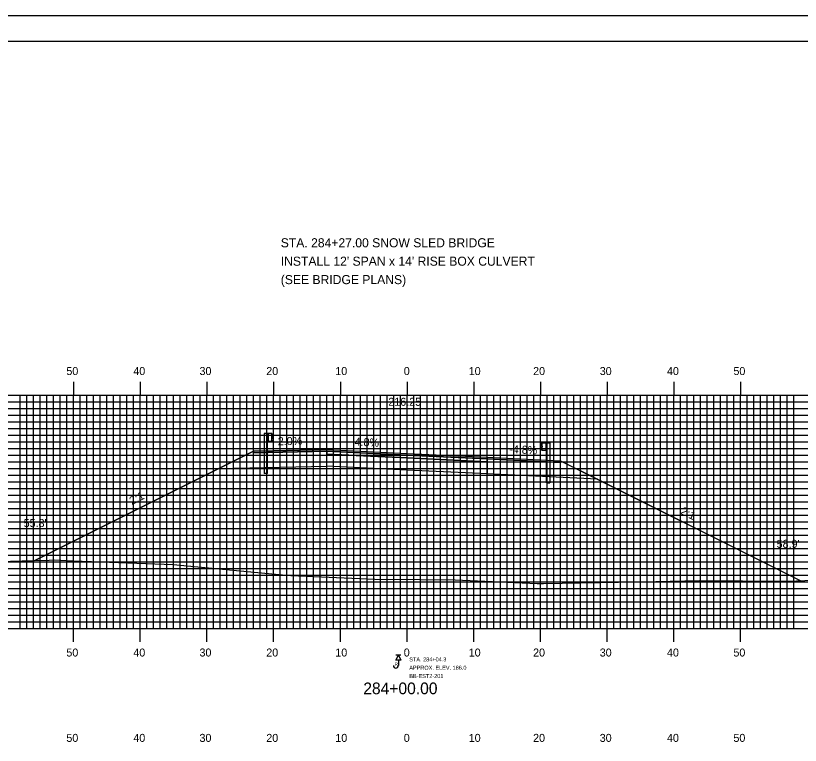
# Model space of a CAD drawing. Extents: x 1811767 to 1812110, y 442591 to 442811.
# Drawn here: x 1811874.3 to 1811991.9, y 442701.2 to 442810.5 of the extents above; entities that cross this region are included whole.
import ezdxf

# ---------------------------------------------------------------- set-up
doc = ezdxf.new("R2010")
doc.units = 0
for name, color, linetype in [('ANNOTATION', 7, 'Continuous'), ('BORDER', 7, 'Continuous'), ('D_Guardrail_Beam_Lt', 7, 'Continuous'), ('D_Guardrail_Beam_Rt', 7, 'Continuous'), ('D_Roadway_Centerline', 7, 'Continuous'), ('D_Roadway_Centerline_Text', 7, 'Continuous'), ('D_Roadway_Edge_Shoulder', 7, 'Continuous'), ('D_Roadway_Edge_TW', 7, 'Continuous'), ('D_Roadway_Pavement', 7, 'Continuous'), ('D_Roadway_SlopeLines', 7, 'Continuous'), ('D_Roadway_SubGrade', 7, 'Continuous'), ('D_Text_Standard', 7, 'Continuous'), ('H_V ANNOTATION', 7, 'Continuous'), ('MAJOR', 7, 'Continuous'), ('MINOR', 7, 'Continuous'), ('PLOT BOUNDARY', 7, 'Continuous'), ('ROCKS', 7, 'Continuous'), ('S_Roadway_Centerline', 7, 'Continuous')]:
    doc.layers.add(name, color=color, linetype=linetype)

msp = doc.modelspace()

# ---------------------------------------------------------------- linework, layer by layer
at = {"layer": 'BORDER'}
msp.add_lwpolyline([(1811783.32, 442596.67), (1812103.32, 442596.67), (1812103.32, 442806.67), (1811783.32, 442806.67)], close=True, dxfattribs=at)
at = {"layer": 'D_Guardrail_Beam_Lt'}
for p, q in [((1811911.49, 442747.91), (1811911.49, 442741.91)), ((1811911.96, 442747.91), (1811911.49, 442747.91)), ((1811912.65, 442747.91), (1811911.96, 442747.91)), ((1811911.96, 442747.91), (1811911.96, 442746.74)), ((1811912.02, 442747.91), (1811912.02, 442746.74)), ((1811912.12, 442747.91), (1811912.12, 442746.74)), ((1811912.65, 442746.74), (1811912.65, 442747.91)), ((1811912.65, 442747.83), (1811912.72, 442747.81)), ((1811912.65, 442747.36), (1811912.65, 442747.29)), ((1811912.88, 442747.56), (1811912.68, 442747.43)), ((1811912.68, 442747.23), (1811912.88, 442747.09)), ((1811912.74, 442747.81), (1811912.88, 442747.71)), ((1811912.88, 442746.95), (1811912.74, 442746.85)), ((1811911.96, 442746.74), (1811912.65, 442746.74)), ((1811911.98, 442741.91), (1811911.98, 442746.74)), ((1811912.72, 442746.84), (1811912.65, 442746.83)), ((1811911.98, 442741.91), (1811911.49, 442741.91))]:
    msp.add_line(p, q, dxfattribs=at)
for centre, major_axis, start_param, end_param in [((1811912.73, 442747.36), (-0.0789, 0), 5.323254, 6.283185), ((1811912.73, 442747.29), (-0.0789, 0), 6.283185, 7.243116), ((1811912.71, 442747.77), (0.0417, 0), 0.959931, 1.376053), ((1811912.83, 442747.63), (0.0877, 0), 5.323254, 7.243116), ((1811912.83, 442747.02), (0.0877, 0), 5.323254, 7.243116), ((1811912.71, 442746.88), (0.0417, 0), 4.907132, 5.323254)]:
    msp.add_ellipse(centre, major_axis=major_axis, ratio=0.995501, start_param=start_param, end_param=end_param, dxfattribs=at)
at = {"layer": 'D_Guardrail_Beam_Rt'}
for p, q in [((1811953.1, 442746.43), (1811952.95, 442746.33)), ((1811952.95, 442746.19), (1811953.15, 442746.05)), ((1811953.15, 442745.85), (1811952.95, 442745.72)), ((1811953.19, 442746.45), (1811953.11, 442746.44)), ((1811953.18, 442745.99), (1811953.18, 442745.92)), ((1811953.19, 442746.53), (1811953.87, 442746.53)), ((1811953.19, 442745.37), (1811953.19, 442746.53)), ((1811953.71, 442746.53), (1811953.71, 442745.37)), ((1811953.81, 442746.53), (1811953.81, 442745.37)), ((1811953.87, 442746.53), (1811954.35, 442746.53)), ((1811953.87, 442746.53), (1811953.87, 442745.37)), ((1811954.35, 442746.53), (1811954.35, 442740.53)), ((1811952.95, 442745.57), (1811953.1, 442745.47)), ((1811953.11, 442745.47), (1811953.19, 442745.45)), ((1811953.87, 442745.37), (1811953.19, 442745.37)), ((1811953.85, 442740.53), (1811953.85, 442745.37)), ((1811953.85, 442740.53), (1811954.35, 442740.53))]:
    msp.add_line(p, q, dxfattribs=at)
for centre, major_axis, start_param, end_param in [((1811953, 442746.26), (-0.0877, 0), 5.323254, 7.243116), ((1811953, 442745.64), (-0.0877, 0), 5.323254, 7.243116), ((1811953.12, 442746.4), (-0.0417, 0), 4.907132, 5.323254), ((1811953.1, 442745.99), (0.0789, 0), 0, 0.959931), ((1811953.1, 442745.92), (0.0789, 0), 5.323254, 6.283185), ((1811953.12, 442745.51), (-0.0417, 0), 0.959931, 1.376053)]:
    msp.add_ellipse(centre, major_axis=major_axis, ratio=0.995501, start_param=start_param, end_param=end_param, dxfattribs=at)
at = {"layer": 'D_Roadway_Centerline'}
msp.add_lwpolyline([(1811877.12, 442728.87), (1811904.71, 442742.66), (1811909.92, 442745.27), (1811912.92, 442745.33), (1811920.92, 442745.49), (1811932.92, 442744.91), (1811944.92, 442744.34), (1811952.92, 442743.95), (1811955.92, 442743.81), (1811961.45, 442741.04), (1811991.84, 442725.85)], dxfattribs=at)
at = {"layer": 'D_Roadway_Edge_Shoulder'}
for points in [[(1811920.92, 442745.49), (1811912.92, 442745.33), (1811912.92, 442745.33), (1811909.92, 442745.27), (1811909.92, 442745.02), (1811920.92, 442745.24)], [(1811944.92, 442744.34), (1811952.92, 442743.95), (1811952.92, 442743.95), (1811955.92, 442743.81), (1811955.92, 442743.56), (1811944.92, 442744.09)]]:
    msp.add_lwpolyline(points, close=True, dxfattribs=at)
at = {"layer": 'D_Roadway_Edge_TW'}
msp.add_lwpolyline([(1811920.92, 442745.24), (1811920.92, 442745.49), (1811932.92, 442744.91), (1811944.92, 442744.34), (1811944.92, 442744.09), (1811932.92, 442744.66)], close=True, dxfattribs=at)
at = {"layer": 'D_Roadway_Pavement'}
msp.add_lwpolyline([(1811920.92, 442744.82), (1811920.92, 442745.24), (1811932.92, 442744.66), (1811944.92, 442744.09), (1811944.92, 442743.67), (1811932.92, 442744.24)], close=True, dxfattribs=at)
for points in [[(1811920.92, 442745.24), (1811920.92, 442744.82)], [(1811944.92, 442744.09), (1811944.92, 442743.67)]]:
    msp.add_lwpolyline(points, dxfattribs=at)
at = {"layer": 'D_Roadway_SlopeLines'}
for points in [[(1811909.92, 442745.27), (1811877.12, 442728.87)], [(1811955.92, 442743.81), (1811991.84, 442725.85)]]:
    msp.add_lwpolyline(points, dxfattribs=at)
at = {"layer": 'D_Roadway_SubGrade'}
for points in [[(1811920.92, 442744.82), (1811920.92, 442745.24), (1811909.92, 442745.02), (1811909.92, 442745.27), (1811904.71, 442742.66), (1811920.92, 442742.99)], [(1811920.92, 442742.99), (1811920.92, 442745.24), (1811920.92, 442744.82), (1811932.92, 442744.24), (1811944.92, 442743.67), (1811944.92, 442744.09), (1811944.92, 442741.84), (1811932.92, 442742.41)], [(1811944.92, 442743.67), (1811944.92, 442744.09), (1811955.92, 442743.56), (1811955.92, 442743.81), (1811961.45, 442741.04), (1811944.92, 442741.84)]]:
    msp.add_lwpolyline(points, close=True, dxfattribs=at)
at = {"layer": 'MAJOR'}
for p, q in [((1811882.92, 442755.67), (1811882.92, 442753.67)), ((1811892.92, 442755.67), (1811892.92, 442753.67)), ((1811902.92, 442755.67), (1811902.92, 442753.67)), ((1811912.92, 442755.67), (1811912.92, 442753.67)), ((1811922.92, 442755.67), (1811922.92, 442753.67)), ((1811932.92, 442755.67), (1811932.92, 442753.67)), ((1811942.92, 442755.67), (1811942.92, 442753.67)), ((1811952.92, 442755.67), (1811952.92, 442753.67)), ((1811962.92, 442755.67), (1811962.92, 442753.67)), ((1811972.92, 442755.67), (1811972.92, 442753.67)), ((1811982.92, 442755.67), (1811982.92, 442753.67)), ((1811792.92, 442753.67), (1812072.92, 442753.67)), ((1811792.92, 442753.67), (1812072.92, 442753.67)), ((1811882.92, 442718.67), (1811882.92, 442753.67)), ((1811892.92, 442718.67), (1811892.92, 442753.67)), ((1811902.92, 442718.67), (1811902.92, 442753.67)), ((1811912.92, 442718.67), (1811912.92, 442753.67)), ((1811922.92, 442718.67), (1811922.92, 442753.67)), ((1811932.92, 442718.67), (1811932.92, 442753.67)), ((1811942.92, 442718.67), (1811942.92, 442753.67)), ((1811952.92, 442718.67), (1811952.92, 442753.67)), ((1811962.92, 442718.67), (1811962.92, 442753.67)), ((1811972.92, 442718.67), (1811972.92, 442753.67)), ((1811982.92, 442718.67), (1811982.92, 442753.67)), ((1811792.92, 442748.67), (1812072.92, 442748.67)), ((1811792.92, 442743.67), (1812072.92, 442743.67)), ((1811792.92, 442738.67), (1812072.92, 442738.67)), ((1811792.92, 442733.67), (1812072.92, 442733.67)), ((1811792.92, 442728.67), (1812072.92, 442728.67)), ((1811792.92, 442723.67), (1812072.92, 442723.67)), ((1811792.92, 442718.67), (1812072.92, 442718.67)), ((1811792.92, 442718.67), (1812072.92, 442718.67)), ((1811882.92, 442716.66), (1811882.92, 442718.67)), ((1811892.92, 442716.66), (1811892.92, 442718.67)), ((1811902.92, 442716.66), (1811902.92, 442718.67)), ((1811912.92, 442716.66), (1811912.92, 442718.67)), ((1811922.92, 442716.66), (1811922.92, 442718.67)), ((1811932.92, 442716.66), (1811932.92, 442718.67)), ((1811942.92, 442716.66), (1811942.92, 442718.67)), ((1811952.92, 442716.66), (1811952.92, 442718.67)), ((1811962.92, 442716.66), (1811962.92, 442718.67)), ((1811972.92, 442716.66), (1811972.92, 442718.67)), ((1811982.92, 442716.66), (1811982.92, 442718.67))]:
    msp.add_line(p, q, dxfattribs=at)
at = {"layer": 'MINOR'}
for p, q in [((1811874.92, 442718.67), (1811874.92, 442753.67)), ((1811875.92, 442718.67), (1811875.92, 442753.67)), ((1811876.92, 442718.67), (1811876.92, 442753.67)), ((1811877.92, 442718.67), (1811877.92, 442753.67)), ((1811878.92, 442718.67), (1811878.92, 442753.67)), ((1811879.92, 442718.67), (1811879.92, 442753.67)), ((1811880.92, 442718.67), (1811880.92, 442753.67)), ((1811881.92, 442718.67), (1811881.92, 442753.67)), ((1811883.92, 442718.67), (1811883.92, 442753.67)), ((1811884.92, 442718.67), (1811884.92, 442753.67)), ((1811885.92, 442718.67), (1811885.92, 442753.67)), ((1811886.92, 442718.67), (1811886.92, 442753.67)), ((1811887.92, 442718.67), (1811887.92, 442753.67)), ((1811888.92, 442718.67), (1811888.92, 442753.67)), ((1811889.92, 442718.67), (1811889.92, 442753.67)), ((1811890.92, 442718.67), (1811890.92, 442753.67)), ((1811891.92, 442718.67), (1811891.92, 442753.67)), ((1811893.92, 442718.67), (1811893.92, 442753.67)), ((1811894.92, 442718.67), (1811894.92, 442753.67)), ((1811895.92, 442718.67), (1811895.92, 442753.67)), ((1811896.92, 442718.67), (1811896.92, 442753.67)), ((1811897.92, 442718.67), (1811897.92, 442753.67)), ((1811898.92, 442718.67), (1811898.92, 442753.67)), ((1811899.92, 442718.67), (1811899.92, 442753.67)), ((1811900.92, 442718.67), (1811900.92, 442753.67)), ((1811901.92, 442718.67), (1811901.92, 442753.67)), ((1811903.92, 442718.67), (1811903.92, 442753.67)), ((1811904.92, 442718.67), (1811904.92, 442753.67)), ((1811905.92, 442718.67), (1811905.92, 442753.67)), ((1811906.92, 442718.67), (1811906.92, 442753.67)), ((1811907.92, 442718.67), (1811907.92, 442753.67)), ((1811908.92, 442718.67), (1811908.92, 442753.67)), ((1811909.92, 442718.67), (1811909.92, 442753.67)), ((1811910.92, 442718.67), (1811910.92, 442753.67)), ((1811911.92, 442718.67), (1811911.92, 442753.67)), ((1811913.92, 442718.67), (1811913.92, 442753.67)), ((1811914.92, 442718.67), (1811914.92, 442753.67)), ((1811915.92, 442718.67), (1811915.92, 442753.67)), ((1811916.92, 442718.67), (1811916.92, 442753.67)), ((1811917.92, 442718.67), (1811917.92, 442753.67)), ((1811918.92, 442718.67), (1811918.92, 442753.67)), ((1811919.92, 442718.67), (1811919.92, 442753.67)), ((1811920.92, 442718.67), (1811920.92, 442753.67)), ((1811921.92, 442718.67), (1811921.92, 442753.67)), ((1811923.92, 442718.67), (1811923.92, 442753.67)), ((1811924.92, 442718.67), (1811924.92, 442753.67)), ((1811925.92, 442718.67), (1811925.92, 442753.67)), ((1811926.92, 442718.67), (1811926.92, 442753.67)), ((1811927.92, 442718.67), (1811927.92, 442753.67)), ((1811928.92, 442718.67), (1811928.92, 442753.67)), ((1811929.92, 442718.67), (1811929.92, 442753.67)), ((1811930.92, 442718.67), (1811930.92, 442753.67)), ((1811931.92, 442718.67), (1811931.92, 442753.67)), ((1811933.92, 442718.67), (1811933.92, 442753.67)), ((1811934.92, 442718.67), (1811934.92, 442753.67)), ((1811935.92, 442718.67), (1811935.92, 442753.67)), ((1811936.92, 442718.67), (1811936.92, 442753.67)), ((1811937.92, 442718.67), (1811937.92, 442753.67)), ((1811938.92, 442718.67), (1811938.92, 442753.67)), ((1811939.92, 442718.67), (1811939.92, 442753.67)), ((1811940.92, 442718.67), (1811940.92, 442753.67)), ((1811941.92, 442718.67), (1811941.92, 442753.67)), ((1811943.92, 442718.67), (1811943.92, 442753.67)), ((1811944.92, 442718.67), (1811944.92, 442753.67)), ((1811945.92, 442718.67), (1811945.92, 442753.67)), ((1811946.92, 442718.67), (1811946.92, 442753.67)), ((1811947.92, 442718.67), (1811947.92, 442753.67)), ((1811948.92, 442718.67), (1811948.92, 442753.67)), ((1811949.92, 442718.67), (1811949.92, 442753.67)), ((1811950.92, 442718.67), (1811950.92, 442753.67)), ((1811951.92, 442718.67), (1811951.92, 442753.67)), ((1811953.92, 442718.67), (1811953.92, 442753.67)), ((1811954.92, 442718.67), (1811954.92, 442753.67)), ((1811955.92, 442718.67), (1811955.92, 442753.67)), ((1811956.92, 442718.67), (1811956.92, 442753.67)), ((1811957.92, 442718.67), (1811957.92, 442753.67)), ((1811958.92, 442718.67), (1811958.92, 442753.67)), ((1811959.92, 442718.67), (1811959.92, 442753.67)), ((1811960.92, 442718.67), (1811960.92, 442753.67)), ((1811961.92, 442718.67), (1811961.92, 442753.67)), ((1811963.92, 442718.67), (1811963.92, 442753.67)), ((1811964.92, 442718.67), (1811964.92, 442753.67)), ((1811965.92, 442718.67), (1811965.92, 442753.67)), ((1811966.92, 442718.67), (1811966.92, 442753.67)), ((1811967.92, 442718.67), (1811967.92, 442753.67)), ((1811968.92, 442718.67), (1811968.92, 442753.67)), ((1811969.92, 442718.67), (1811969.92, 442753.67)), ((1811970.92, 442718.67), (1811970.92, 442753.67)), ((1811971.92, 442718.67), (1811971.92, 442753.67)), ((1811973.92, 442718.67), (1811973.92, 442753.67)), ((1811974.92, 442718.67), (1811974.92, 442753.67)), ((1811975.92, 442718.67), (1811975.92, 442753.67)), ((1811976.92, 442718.67), (1811976.92, 442753.67)), ((1811977.92, 442718.67), (1811977.92, 442753.67)), ((1811978.92, 442718.67), (1811978.92, 442753.67)), ((1811979.92, 442718.67), (1811979.92, 442753.67)), ((1811980.92, 442718.67), (1811980.92, 442753.67)), ((1811981.92, 442718.67), (1811981.92, 442753.67)), ((1811983.92, 442718.67), (1811983.92, 442753.67)), ((1811984.92, 442718.67), (1811984.92, 442753.67)), ((1811985.92, 442718.67), (1811985.92, 442753.67)), ((1811986.92, 442718.67), (1811986.92, 442753.67)), ((1811987.92, 442718.67), (1811987.92, 442753.67)), ((1811988.92, 442718.67), (1811988.92, 442753.67)), ((1811989.92, 442718.67), (1811989.92, 442753.67)), ((1811990.92, 442718.67), (1811990.92, 442753.67)), ((1811792.92, 442752.67), (1812072.92, 442752.67)), ((1811792.92, 442751.67), (1812072.92, 442751.67)), ((1811792.92, 442750.67), (1812072.92, 442750.67)), ((1811792.92, 442749.67), (1812072.92, 442749.67)), ((1811792.92, 442747.67), (1812072.92, 442747.67)), ((1811792.92, 442746.67), (1812072.92, 442746.67)), ((1811792.92, 442745.67), (1812072.92, 442745.67)), ((1811792.92, 442744.67), (1812072.92, 442744.67)), ((1811792.92, 442742.67), (1812072.92, 442742.67)), ((1811792.92, 442741.67), (1812072.92, 442741.67)), ((1811792.92, 442740.67), (1812072.92, 442740.67)), ((1811792.92, 442739.67), (1812072.92, 442739.67)), ((1811792.92, 442737.67), (1812072.92, 442737.67)), ((1811792.92, 442736.67), (1812072.92, 442736.67)), ((1811792.92, 442735.67), (1812072.92, 442735.67)), ((1811792.92, 442734.67), (1812072.92, 442734.67)), ((1811792.92, 442732.67), (1812072.92, 442732.67)), ((1811792.92, 442731.67), (1812072.92, 442731.67)), ((1811792.92, 442730.67), (1812072.92, 442730.67)), ((1811792.92, 442729.67), (1812072.92, 442729.67)), ((1811792.92, 442727.67), (1812072.92, 442727.67)), ((1811792.92, 442726.67), (1812072.92, 442726.67)), ((1811792.92, 442725.67), (1812072.92, 442725.67)), ((1811792.92, 442724.67), (1812072.92, 442724.67)), ((1811792.92, 442722.67), (1812072.92, 442722.67)), ((1811792.92, 442721.67), (1812072.92, 442721.67)), ((1811792.92, 442720.67), (1812072.92, 442720.67)), ((1811792.92, 442719.67), (1812072.92, 442719.67))]:
    msp.add_line(p, q, dxfattribs=at)
at = {"layer": 'PLOT BOUNDARY'}
msp.add_lwpolyline([(1811767.13, 442590.55), (1812107.13, 442590.55), (1812107.13, 442810.55), (1811767.13, 442810.55)], close=True, dxfattribs=at)
at = {"layer": 'ROCKS'}
for p, q in [((1811931.98, 442714.67), (1811931.25, 442714.67)), ((1811931.62, 442713.93), (1811931.62, 442713.11))]:
    msp.add_line(p, q, dxfattribs=at)
msp.add_lwpolyline([(1811931.62, 442714.67), (1811931.98, 442713.93), (1811931.25, 442713.93)], close=True, dxfattribs=at)
msp.add_arc((1811931.24, 442713.11), 0.373, 180, 0, dxfattribs=at)
at = {"layer": 'S_Roadway_Centerline'}
msp.add_lwpolyline([(1811861.44, 442728.43), (1811876.92, 442728.86), (1811879.28, 442728.94), (1811880.11, 442728.97), (1811882.85, 442728.82), (1811897.88, 442728.29), (1811914.26, 442726.71), (1811915.52, 442726.63), (1811928.09, 442726.07), (1811934.83, 442726), (1811940.13, 442725.97), (1811952.44, 442725.4), (1811953.36, 442725.42), (1811970.2, 442725.74), (1811976.7, 442725.87), (1811989.7, 442725.78), (1811990.06, 442725.78), (1812001.38, 442726.22)], dxfattribs=at)

# ---------------------------------------------------------------- texts
at = {"layer": 'ANNOTATION'}
for s, p in [('STA. 284+27.00 SNOW SLED BRIDGE', (1811913.99, 442775.82)), ("INSTALL 12' SPAN x 14' RISE BOX CULVERT", (1811913.99, 442773.06)), ('(SEE BRIDGE PLANS)', (1811913.99, 442770.3))]:
    msp.add_text(s, height=1.36, dxfattribs=at).set_placement(p)
for s, rotation, p in [('-2.0%', 1.1458, (1811913.02, 442746.13)), ('4.8%', 357.2519, (1811925.04, 442746.09)), ('-4.8%', 357.2519, (1811948.22, 442744.98)), ('2:1', 26.5651, (1811891.66, 442737.18)), ('2:1', 333.4349, (1811973.81, 442735.9))]:
    msp.add_text(s, height=1.2, rotation=rotation, dxfattribs=at).set_placement(p)
at = {"layer": 'D_Roadway_Centerline'}
for s, p in [('C', (1811932.91, 442744.91)), ('L', (1811932.92, 442744.9))]:
    msp.add_text(s, height=0.0146, dxfattribs=at).set_placement(p)
at = {"layer": 'D_Roadway_Centerline_Text'}
msp.add_text('216.25', height=1.2, dxfattribs=at).set_placement((1811930.12, 442752.06))
at = {"layer": 'D_Text_Standard'}
for s, p in [("55.8'", (1811875.45, 442733.88)), ("58.9'", (1811988.33, 442730.76))]:
    msp.add_text(s, height=1.2, dxfattribs=at).set_placement(p)
at = {"layer": 'H_V ANNOTATION'}
for s, height, p in [('50', 1.2, (1811881.85, 442756.67)), ('40', 1.2, (1811891.89, 442756.67)), ('30', 1.2, (1811901.81, 442756.67)), ('20', 1.2, (1811911.82, 442756.67)), ('10', 1.2, (1811922.17, 442756.67)), ('0', 1.2, (1811932.43, 442756.67)), ('10', 1.2, (1811942.17, 442756.67)), ('20', 1.2, (1811951.82, 442756.67)), ('30', 1.2, (1811961.81, 442756.67)), ('40', 1.2, (1811971.89, 442756.67)), ('50', 1.2, (1811981.85, 442756.67)), ('50', 1.2, (1811881.85, 442714.47)), ('40', 1.2, (1811891.89, 442714.47)), ('30', 1.2, (1811901.81, 442714.47)), ('20', 1.2, (1811911.82, 442714.47)), ('10', 1.2, (1811922.17, 442714.47)), ('0', 1.2, (1811932.43, 442714.47)), ('10', 1.2, (1811942.17, 442714.47)), ('20', 1.2, (1811951.82, 442714.47)), ('30', 1.2, (1811961.81, 442714.47)), ('40', 1.2, (1811971.89, 442714.47)), ('50', 1.2, (1811981.85, 442714.47)), ('284+00.00', 1.75, (1811926.36, 442708.82)), ('50', 1.2, (1811881.85, 442701.67)), ('40', 1.2, (1811891.89, 442701.67)), ('30', 1.2, (1811901.81, 442701.67)), ('20', 1.2, (1811911.82, 442701.67)), ('10', 1.2, (1811922.17, 442701.67)), ('0', 1.2, (1811932.43, 442701.67)), ('10', 1.2, (1811942.17, 442701.67)), ('20', 1.2, (1811951.82, 442701.67)), ('30', 1.2, (1811961.81, 442701.67)), ('40', 1.2, (1811971.89, 442701.67)), ('50', 1.2, (1811981.85, 442701.67))]:
    msp.add_text(s, height=height, dxfattribs=at).set_placement(p)
at = {"layer": 'ROCKS'}
for s, p in [('STA. 284+04.3', (1811933.26, 442713.74)), ('APPROX. ELEV. 186.0', (1811933.26, 442712.49)), ('BB-EST2-201', (1811933.26, 442711.24))]:
    msp.add_text(s, height=0.6, rotation=360, dxfattribs=at).set_placement(p)
msp.add_text('R', height=0.492, dxfattribs=at).set_placement((1811931.07, 442713.07))

doc.saveas('drawing.dxf')
